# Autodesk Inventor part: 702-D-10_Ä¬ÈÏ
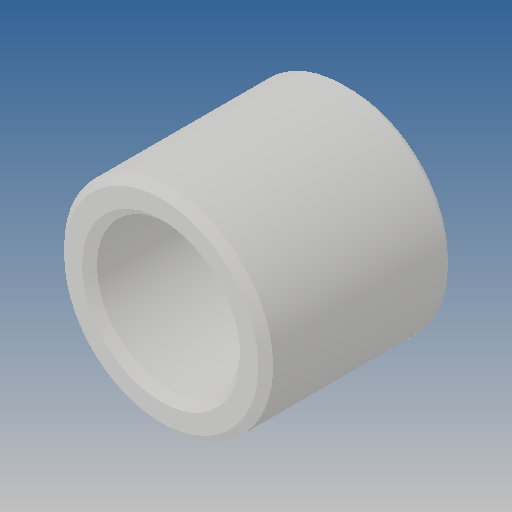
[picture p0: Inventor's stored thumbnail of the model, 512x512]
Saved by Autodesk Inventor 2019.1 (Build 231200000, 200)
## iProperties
Created: 2010-06
Part Number: 702-D-10_Ä¬ÈÏ
Material: Ogólny
Document SubType Name: Modeling
Designer: CADENGINEERING4
Density: 1 g/cm^3
Appearance: Domyślna
Author: CADENGINEERING4
Revision Number: ÈÎºÎ
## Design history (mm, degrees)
feature "NONE"
node "Bryła1"
